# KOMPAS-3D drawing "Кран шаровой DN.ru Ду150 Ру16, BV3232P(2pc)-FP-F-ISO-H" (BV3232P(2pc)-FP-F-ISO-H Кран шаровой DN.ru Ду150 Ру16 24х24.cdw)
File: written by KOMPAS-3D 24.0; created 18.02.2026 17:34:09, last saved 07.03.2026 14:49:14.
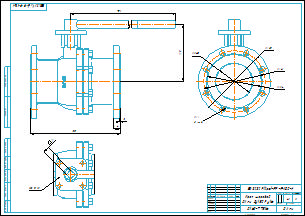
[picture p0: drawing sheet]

Document properties: Автор: R2D2; Форматы листов документа: A2; Полное имя файла: BV3232P(2pc)-FP-F-ISO-H Кран шаровой DN.ru Ду150 Ру16 24х24.m3d; Масса: 41; Наименование: Кран шаровой DN.ru Ду150 Ру16; Количество листов документа: 1; Примечание: D160-77516

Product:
- Part/product: Кран шаровой DN.ru Ду150 Ру16  | designation BV3232P(2pc)-FP-F-ISO-H
    Масса: 41
    Раздел спецификации: Прочие изделия
    Примечание: D160-77516

Views: Вид 1, Справа
Referenced files in E:\Работа\Зайцев\BV3232P(2pc)-FP-F-ISO-H Кран шаровой DN.ru Ду15-300 Ру16-40\DN150 PN16 27х27\: BV3232P(2pc)-FP-F-ISO-H Кран шаровой DN.ru Ду150 Ру16 27х27.m3d
Referenced files in E:\Работа\Зайцев\BV3232P(2pc)-FP-F-ISO-H Кран шаровой DN.ru Ду15-300 Ру16-40\DN150 PN16 24х24\: BV3232P(2pc)-FP-F-ISO-H Кран шаровой DN.ru Ду150 Ру16 24х24.m3d
Referenced files in E:\Работа\Зайцев\Для компаса\: чертеж DN.ru А3.cdt
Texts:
  BV3232P(2pc)-FP-F-ISO-H
  чертеж DN.ru А3.cdt
  Кран шаровой
  DN.ru Ду150 Ру16
  Кран шаровой DN.ru Ду150 Ру16
  BV3232P(2pc)-FP-F-ISO-H Кран шаровой DN.ru Ду150 Ру16
Dimensions and other numbers on the sheet: 0; 3; 2; 4; 350; 24; 223; 750; 1:2; 1; 41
